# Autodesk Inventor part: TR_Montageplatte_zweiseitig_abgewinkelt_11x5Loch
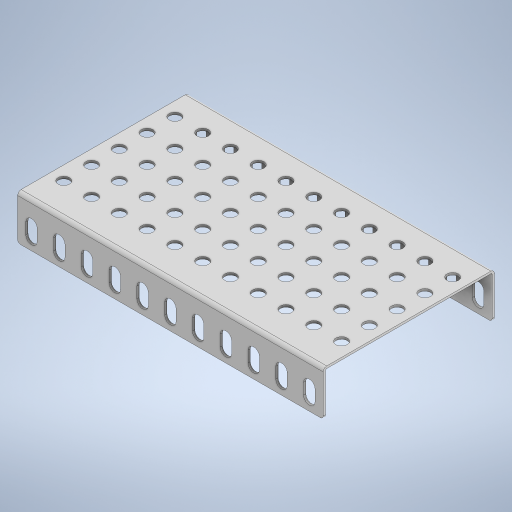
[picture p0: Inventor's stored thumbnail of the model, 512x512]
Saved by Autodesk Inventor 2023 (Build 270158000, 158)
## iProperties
Created: 2023-11
Part Number: TR_Montageplatte_zweiseitig_abgewinkelt_11x5Loch
Material: Generisch
Document SubType Name: Modeling
Designer: Greiner
Density: 1 g/cm^3
Appearance: Vorgabe
Author: Greiner
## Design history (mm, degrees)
sketch "Skizze1"
  geometry: L1 (0, 30)-(14.75, 30); L2 (15.2, 29.55)-(15.2, -29.55); L3 (14.75, -30)-(0, -30); L4 (0, -30)-(0, -30.8); L5 (0, -30.8)-(14.75, -30.8); L6 (16, -29.55)-(16, 29.55); L7 (14.75, 30.8)-(0, 30.8); L8 (0, 30.8)-(0, 30); A1 r 0.45 centre (14.75, 29.55) between (15.2, 29.55) and (14.75, 30); A2 r 0.45 centre (14.75, -29.55) between (14.75, -30) and (15.2, -29.55); A3 r 1.25 centre (14.75, 29.55) between (16, 29.55) and (14.75, 30.8); A4 r 1.25 centre (14.75, -29.55) between (14.75, -30.8) and (16, -29.55); 2 further points
  constraints: 16 end point, 8 point on circle, 8 tangent, 5 perpendicular, 4 centre point, 2 coincident, 2 equal radius, 2 point on line, 1 horizontal, 1 horizontal alignment, 1 midpoint, 1 vertical alignment
  dimensions: "d3" = 60 distance between parallel lines of L3 L1 (= Lochy + Einheitsmaß); "d4" = 0.8 distance between parallel lines of L1 L7; "d5" = 1.25 radius of A3; "d6" = 16 distance from line of L7.end L6
extrude "Extrusion1" new body sketch "Skizze1" stored distance "d7" = 110 (computed from Lochx, Einheitsmaß); taper "d8" = 0 deg
sketch "Skizze2"
  geometry: L1 (0, 0)-(110, 0) reference; L2 (110, 14.75)-(110, 0) reference; L3 (105, 4)-(105, 8); L4 (107.075, 4)-(107.075, 8); L5 (102.925, 8)-(102.925, 4); A1 r 2.075 centre (105, 4) between (102.925, 4) and (107.075, 4); A2 r 2.075 centre (105, 8) between (107.075, 8) and (102.925, 8); 4 further points
  constraints: 8 end point, 4 point on circle, 4 tangent, 3 midpoint, 2 centre point, 1 parallel, 1 vertical
  dimensions: "d32" = 4 distance of L3.start L3.end (= 2 x Breitloch); "d33" = 4.15 diameter of A2 (= 2 x Radius); "d34" = 6 distance from line of L1 point (105, 6); "d35" = 5 distance from line of L2 point (105, 6) (= 0.5 x Einheitsmaß)
extrude "Extrusion2" cut sketch "Skizze2" extent not by distance; stored distance "d11" = 0; taper "d12" = 0 deg
pattern_linear "Rechteckige Anordnung2" dims "d22" = 10 (= Einheitsmaß)
sketch "Skizze3"
  geometry: L1 (110, 59.1)-(110, 0) reference; L2 (0, 60.35)-(110, 60.35) reference; C1 r 2.075 at (105, 50.35); 1 further point
  constraints: 1 centre point
  dimensions: "d16" = 4.15 diameter of C1 (= 2 x Radius); "d17" = 5 distance from line of C1.centre L1 (= 0.5 x Einheitsmaß); "d18" = 10 distance from line of L2 C1.centre (= Einheitsmaß)
extrude "Extrusion3" cut sketch "Skizze3" extent not by distance; stored distance "d23" = 0; taper "d24" = 0 deg
fillet "Rundung1" dims "d31" = 1
node "Volumenkörper1"
pattern_linear "Rechteckige Anordnung3" dims "d27" = 10 (= Einheitsmaß), "d30" = 10 (= Einheitsmaß)
other parameters: "Einheitsmaß" = 10 [user parameter; used in 8 equation terms], "Radius" = 2.075 [user parameter; used in 2 equation terms], "Fasen" = 0.5 [user parameter], "Dicke" = 0.8 [user parameter], "Breitloch" = 2 [user parameter; used in 1 equation term], "Langloch" = 32 [user parameter], "AchteckUmkreis" = 6 [user parameter], "DAchsAufnahme" = 4.1 [user parameter], "AchsDurchmesser" = 4 [user parameter], "AchsFase" = 0.5 [user parameter], "Lochy" = 50 [user parameter; used in 2 equation terms]
